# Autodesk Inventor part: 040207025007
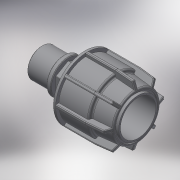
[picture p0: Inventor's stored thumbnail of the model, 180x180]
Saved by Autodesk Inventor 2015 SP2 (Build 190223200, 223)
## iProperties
Created: 2017-08
Part Number: 040207025007
Material: Generic
Description: PLASSON IRRIFIT ADAPTOR 25-3/4"M
Document SubType Name: Modeling
Designer: KIM
Density: 1 g/cm^3
Appearance: Default
Author: KIM
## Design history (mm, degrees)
derived "040207.ipt"
feature "Solid1::040207.ipt"
tag "TaggingFeature1"
body "Solid1"
other parameters: "d5" = 36.4, "d6" = 16.06, "d10" = 45, "d22" = 26.441, "d24" = 1.679, "d25" = 40.5, "d26" = 36, "d31" = 1, "d49" = 2.25, "d50" = 0, "d58" = 0.5, "d61" = 360 deg, "d77" = 25, "d78" = 5 deg, "d80" = 27.5, "d81" = 36.5, "d82" = 2.19, "d84" = 5 deg, "d85" = 70 deg, "d86" = 42.75, "d87" = 0.365, "d88" = 0, "d89" = 38.25, "d90" = 3.65, "d91" = 0, "d99" = 26.441, "d100" = 17, "d101" = 3.4, "d102" = 73, "d103" = 31.7292, "d104" = 0.52882, "d108" = 0, "d109" = 0.26441, "d112" = 21.1528, "d113" = 29.12, "d_" = 25, "E_" = 45, "H_" = 73, "l_nut" = 36.4, "l_" = 17, "R_" = 26.441
